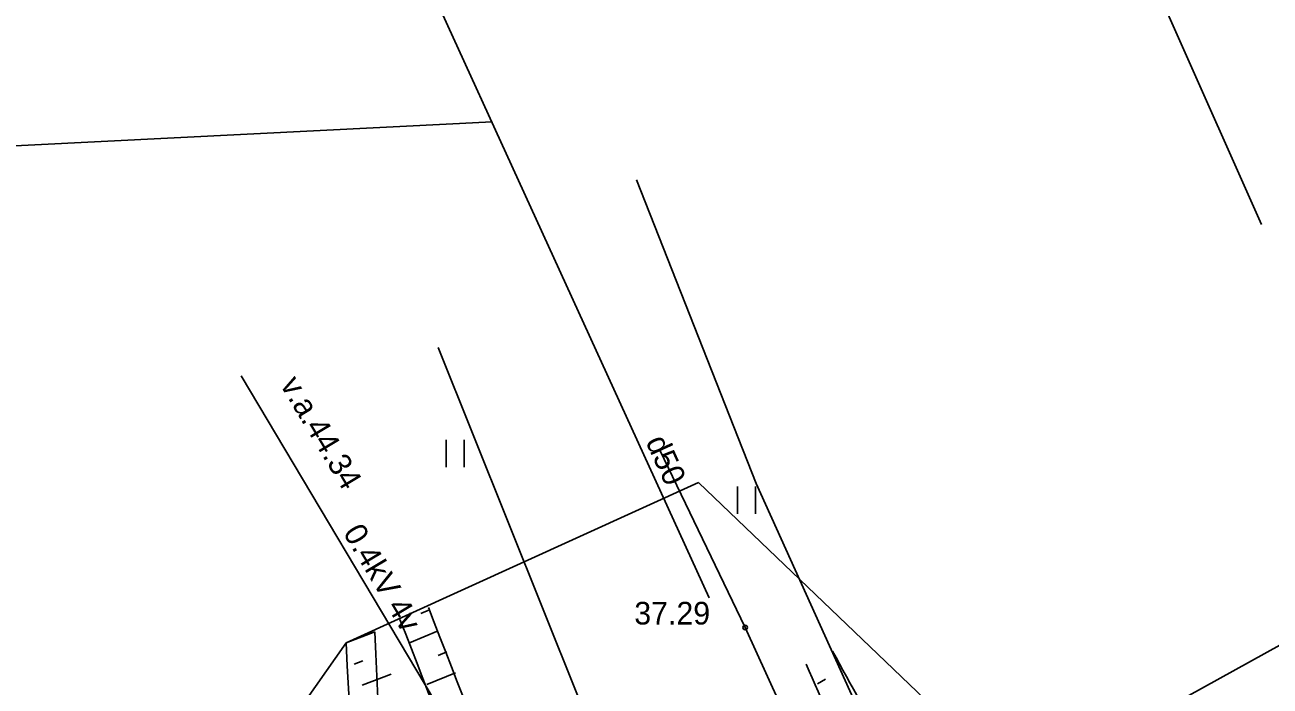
# Model space of a CAD drawing. Extents: x 469981 to 472086, y 246785 to 247785.
# Drawn here: x 471324.7 to 471352.16, y 247360.25 to 247374.84 of the extents above; entities that cross this region are included whole.
import ezdxf

# ---------------------------------------------------------------- set-up
doc = ezdxf.new("R2010")
doc.units = 0
for name, color, linetype in [('CELI_CMAL_####_####_#', 7, 'Continuous'), ('DREN_VADP_####_####_#', 7, 'Continuous'), ('DREN_VADP_####_TKST_#', 7, 'Continuous'), ('ELEK_VADV_ZSPR_####_#', 7, 'Continuous'), ('ELEK_VADV_ZSPR_TKST_#', 7, 'Continuous'), ('NORB_ZOGS_SETA_####_#', 7, 'Continuous'), ('RAMI_UZMR_####_####_#', 7, 'Continuous'), ('RELJ_AATZ_####_TKST_#', 7, 'Continuous'), ('RELJ_ELEM_####_####_#', 7, 'Continuous'), ('RELJ_NOGA_####_####_#', 7, 'Continuous'), ('RELJ_NOGL_####_####_#', 7, 'Continuous'), ('TERT_ELEM_####_####_#', 7, 'Continuous')]:
    doc.layers.add(name, color=color, linetype=linetype)

msp = doc.modelspace()

# ---------------------------------------------------------------- linework, layer by layer
at = {"layer": 'CELI_CMAL_####_####_#'}
for points in [[(471338.703, 247365.456), (471340.587, 247361.545), (471343.087, 247356.058), (471343.774, 247355.226), (471347.4, 247352.573), (471349.509, 247351.696), (471351.575, 247351.992), (471374.262, 247365.343), (471396.093, 247379.507), (471423.487, 247397.08), (471444.29, 247410.189)], [(471014.161, 247188.048), (471038.308, 247191.645), (471077.61, 247195.71), (471090.836, 247197.337), (471096.461, 247198.582), (471117.856, 247206.682), (471130.197, 247213.261), (471151.631, 247225.738), (471175.407, 247239.608), (471196.168, 247252.49), (471217.229, 247265.52), (471244.784, 247283.359), (471266.102, 247296.914), (471293.433, 247314.365), (471318.262, 247330.084), (471336.637, 247341.969), (471339.45, 247343.841), (471340.412, 247346.293), (471340.291, 247349.818), (471339.894, 247353.24), (471336.901, 247360.015), (471333.813, 247367.721)]]:
    msp.add_lwpolyline(points, dxfattribs=at)
at = {"layer": 'DREN_VADP_####_####_#'}
for points in [[(471342.26, 247392.292), (471351.975, 247370.433)], [(471339.793, 247362.2), (471329.668, 247384.371)], [(471334.998, 247372.699), (471334.284, 247372.664), (471305.886, 247371.238)]]:
    msp.add_lwpolyline(points, dxfattribs=at)
at = {"layer": 'ELEK_VADV_ZSPR_####_#'}
msp.add_line((471337.906, 247352.95), (471329.468, 247367.094), dxfattribs=at)
at = {"layer": 'NORB_ZOGS_SETA_####_#'}
msp.add_lwpolyline([(471338.191, 247371.418), (471340.829, 247364.724), (471343.446, 247358.927), (471345.223, 247355.65), (471348.355, 247353.823), (471351.949, 247353.222), (471384.164, 247372.751)], dxfattribs=at)
at = {"layer": 'RAMI_UZMR_####_####_#'}
msp.add_lwpolyline([(471010.572, 247199.465), (471044.448, 247201.846), (471094.566, 247205.368), (471219.251, 247279.294), (471287.982, 247320.045), (471329.582, 247346.385), (471332.466, 247352.407), (471329.951, 247358.592), (471331.784, 247361.204), (471339.558, 247364.746), (471343.514, 247360.959), (471346.629, 247357.978), (471355.9, 247363.1), (471457.4, 247429.3)], dxfattribs=at)
at = {"layer": 'RELJ_ELEM_####_####_#'}
msp.add_circle((471340.587, 247361.545), 0.05, dxfattribs=at)
at = {"layer": 'RELJ_NOGA_####_####_#'}
for p, q in [((471333.625, 247361.932), (471333.436, 247361.854)), ((471331.784, 247361.204), (471332.42, 247361.447)), ((471333.815, 247361.47), (471333.186, 247361.21)), ((471334.006, 247361.007), (471333.817, 247360.93)), ((471331.962, 247360.736), (471332.153, 247360.809)), ((471332.141, 247360.269), (471332.777, 247360.512)), ((471334.197, 247360.545), (471333.567, 247360.286)), ((471342.183, 247360.303), (471342.362, 247360.406))]:
    msp.add_line(p, q, dxfattribs=at)
for points in [[(471341.934, 247360.736), (471344.51, 247356.259), (471349.946, 247353.745), (471355.895, 247354.991), (471376.693, 247368.011), (471396.058, 247380.323), (471444.047, 247411.052), (471471.484, 247428.432), (471497.591, 247445.096), (471529.061, 247465.658), (471552.024, 247480.39), (471579.849, 247498.336), (471608.29, 247516.955), (471640.013, 247537.434), (471663.526, 247552.835), (471700.309, 247577.155), (471731.58, 247596.998), (471755.893, 247610.638), (471758.96, 247612.207)], [(471331.784, 247361.204), (471336.218, 247349.595), (471337.471, 247349.602), (471338.313, 247350.297), (471338.12, 247351.038), (471333.603, 247361.984)]]:
    msp.add_spline(points, degree=3, dxfattribs=at)
at = {"layer": 'RELJ_NOGL_####_####_#'}
for points in [[(471342.514, 247361.025), (471345.404, 247356.891), (471350.224, 247354.862), (471355.251, 247356.423), (471376.007, 247368.362), (471395.596, 247380.988), (471443.663, 247411.567), (471471.284, 247429.247), (471497.369, 247445.866), (471528.273, 247466.831), (471551.61, 247481.241), (471579.417, 247499.099), (471607.686, 247517.412), (471639.588, 247538.317), (471662.844, 247553.564), (471699.582, 247577.982), (471731.348, 247598.063), (471755.711, 247611.433), (471758.267, 247612.728)], [(471332.42, 247361.447), (471336.686, 247350.279), (471337.225, 247350.282), (471337.544, 247350.545), (471337.472, 247350.822), (471332.974, 247361.724)]]:
    msp.add_spline(points, degree=3, dxfattribs=at)
at = {"layer": 'TERT_ELEM_####_####_#'}
for p, q in [((471333.991, 247365.082), (471333.991, 247365.682)), ((471334.391, 247365.082), (471334.391, 247365.682)), ((471340.418, 247364.053), (471340.418, 247364.653)), ((471340.818, 247364.053), (471340.818, 247364.653))]:
    msp.add_line(p, q, dxfattribs=at)

# ---------------------------------------------------------------- texts
at = {"layer": 'DREN_VADP_####_TKST_#'}
msp.add_text('d50', height=0.5, rotation=294.5438, dxfattribs=at).set_placement((471338.384, 247365.646))
at = {"layer": 'ELEK_VADV_ZSPR_TKST_#'}
for s, p in [('v.a.44.34', (471330.319, 247366.904)), ('0.4kV 4v', (471331.705, 247363.636))]:
    msp.add_text(s, height=0.5, rotation=300.8191, dxfattribs=at).set_placement(p)
at = {"layer": 'RELJ_AATZ_####_TKST_#'}
msp.add_text('37.29', height=0.5, dxfattribs=at).set_placement((471338.141, 247361.611))

doc.saveas('drawing.dxf')
